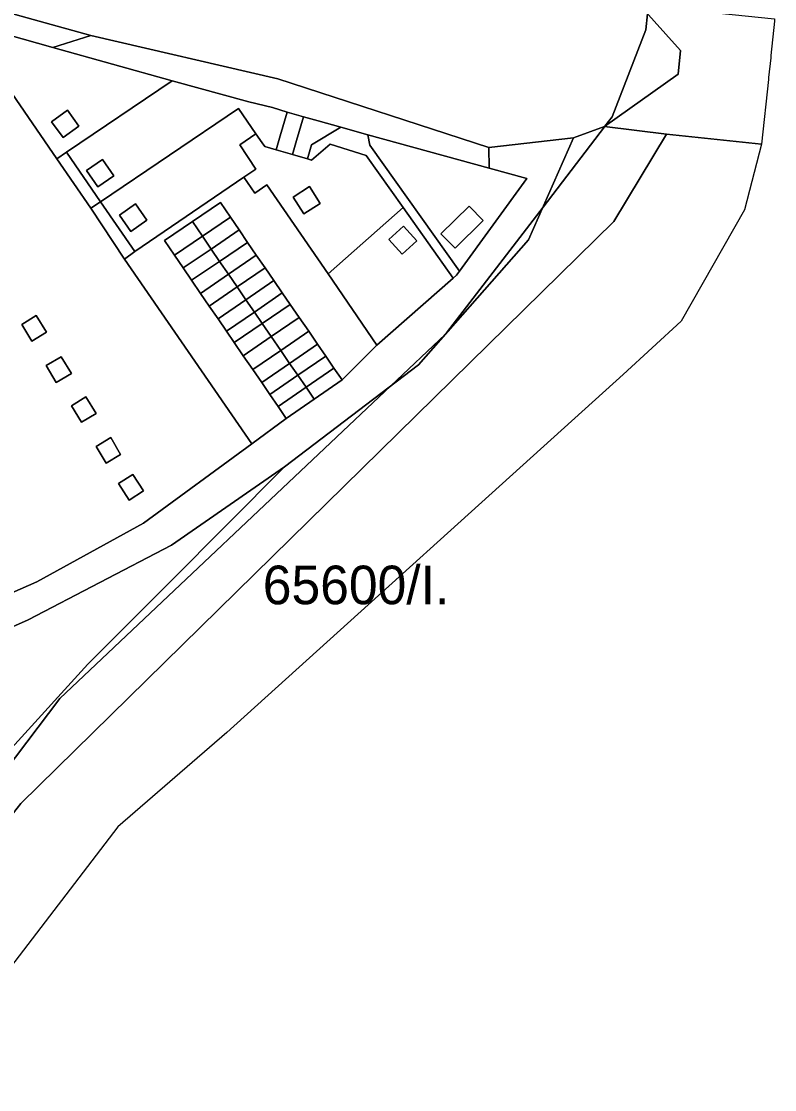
# Model space of a CAD drawing. Extents: x -502026 to -497664, y -1143484 to -1138019.
# Drawn here: x -497820 to -497663.8, y -1140882.6 to -1140661.2 of the extents above; entities that cross this region are included whole.
import ezdxf

# ---------------------------------------------------------------- set-up
doc = ezdxf.new("R2010")
doc.units = 0
for name, color, linetype in [('25', 7, 'Continuous'), ('37', 7, 'Continuous'), ('49', 7, 'Continuous'), ('55', 7, 'Continuous'), ('62', 7, 'Continuous'), ('7', 7, 'Continuous')]:
    doc.layers.add(name, color=color, linetype=linetype)

msp = doc.modelspace()

# ---------------------------------------------------------------- linework, layer by layer
at = {"layer": '25'}
for points in [[(-497805.55, -1140664.16), (-497813.42, -1140666.63), (-497832.11, -1140661.41), (-497812.62, -1140689.68), (-497805.57, -1140699.94), (-497798.59, -1140710.5), (-497772.17, -1140748.77), (-497794.67, -1140765.2), (-497816.79, -1140777.36), (-497824.82, -1140780.89), (-497825.15, -1140780.18), (-497841.74, -1140744.45), (-497858.43, -1140708.44), (-497861.67, -1140701.6), (-497877.43, -1140665.94), (-497897.52, -1140673.81), (-497916.16, -1140638.1), (-497908.61, -1140635.26), (-497911.38, -1140628.95), (-497891.85, -1140619.36), (-497883.28, -1140625.68), (-497860.05, -1140644.73), (-497839.03, -1140654.82)], [(-497814.79, -1140725.62), (-497816.92, -1140722.2), (-497819.9, -1140724.05), (-497817.78, -1140727.49)], [(-497809.61, -1140734.21), (-497811.69, -1140730.73), (-497814.8, -1140732.5), (-497812.75, -1140736.05)], [(-497804.5, -1140742.48), (-497806.63, -1140739.05), (-497809.61, -1140740.89), (-497807.51, -1140744.29)], [(-497799.39, -1140750.98), (-497801.41, -1140747.43), (-497804.48, -1140749.3), (-497802.41, -1140752.77)], [(-497794.69, -1140758.46), (-497796.88, -1140755.08), (-497799.83, -1140756.99), (-497797.64, -1140760.41)]]:
    msp.add_lwpolyline(points, close=True, dxfattribs=at)
at = {"layer": '37'}
for points in [[(-497813.42, -1140666.63), (-497788.69, -1140673.54), (-497810.63, -1140688.34), (-497812.62, -1140689.68), (-497832.11, -1140661.41)], [(-497723.05, -1140687.37), (-497722.99, -1140691.64), (-497748.17, -1140684.73), (-497753.73, -1140683.13), (-497758.48, -1140681.82), (-497761.46, -1140681.02), (-497764.9, -1140680.06), (-497767.93, -1140679.05), (-497772.82, -1140677.87), (-497788.69, -1140673.54), (-497813.42, -1140666.63), (-497805.55, -1140664.16), (-497766.84, -1140673.11)], [(-497764.9, -1140680.06), (-497766.31, -1140684.95), (-497767.16, -1140687.87), (-497769.5, -1140687.17), (-497770.07, -1140686.37), (-497771.35, -1140684.52), (-497774.94, -1140679.25), (-497803.58, -1140698.6), (-497810.63, -1140688.34), (-497788.69, -1140673.54), (-497772.82, -1140677.87), (-497767.93, -1140679.05)], [(-497808.03, -1140682.91), (-497810.44, -1140679.64), (-497813.72, -1140682.05), (-497811.31, -1140685.32)], [(-497771.35, -1140684.52), (-497774.68, -1140686.78), (-497771.36, -1140691.82), (-497773.83, -1140693.5), (-497796.43, -1140708.94), (-497803.58, -1140698.6), (-497774.94, -1140679.25)], [(-497761.46, -1140681.02), (-497762.91, -1140685.94), (-497763.75, -1140688.84), (-497767.16, -1140687.87), (-497766.31, -1140684.95), (-497764.9, -1140680.06)], [(-497753.73, -1140683.13), (-497759.86, -1140686.8), (-497760.69, -1140689.73), (-497763.75, -1140688.84), (-497762.91, -1140685.94), (-497761.46, -1140681.02), (-497758.48, -1140681.82)], [(-497767.16, -1140687.87), (-497763.75, -1140688.84), (-497760.69, -1140689.73), (-497759.83, -1140689.95), (-497755.93, -1140686.66), (-497748.49, -1140689), (-497740.84, -1140699.76), (-497756.35, -1140713.53), (-497769.08, -1140695.11), (-497771.55, -1140696.82), (-497773.83, -1140693.5), (-497771.36, -1140691.82), (-497774.68, -1140686.78), (-497771.35, -1140684.52), (-497770.07, -1140686.37), (-497769.5, -1140687.17)], [(-497748.17, -1140684.73), (-497747.74, -1140686.86), (-497729.17, -1140712.99), (-497729.76, -1140713.83), (-497730.5, -1140714.46), (-497740.84, -1140699.76), (-497748.49, -1140689), (-497755.93, -1140686.66), (-497759.83, -1140689.95), (-497760.69, -1140689.73), (-497759.86, -1140686.8), (-497753.73, -1140683.13)], [(-497722.99, -1140691.64), (-497715.23, -1140693.81), (-497729.17, -1140712.99), (-497747.74, -1140686.86), (-497748.17, -1140684.73)], [(-497803.58, -1140698.6), (-497805.57, -1140699.94), (-497812.62, -1140689.68), (-497810.63, -1140688.34)], [(-497800.84, -1140693.2), (-497803.17, -1140689.85), (-497806.48, -1140692.15), (-497804.15, -1140695.5)], [(-497756.35, -1140713.53), (-497746.3, -1140728.34), (-497753.47, -1140735.53), (-497755.17, -1140733.05), (-497756.86, -1140730.58), (-497758.56, -1140728.1), (-497760.41, -1140725.42), (-497762.39, -1140722.56), (-497764.23, -1140719.92), (-497765.89, -1140717.49), (-497767.64, -1140714.93), (-497769.45, -1140712.29), (-497771.27, -1140709.66), (-497773.09, -1140707.01), (-497774.82, -1140704.44), (-497776.61, -1140701.8), (-497778.72, -1140698.77), (-497784.51, -1140702.69), (-497790.29, -1140706.6), (-497788.22, -1140709.66), (-497786.43, -1140712.3), (-497784.7, -1140714.86), (-497782.83, -1140717.58), (-497781.02, -1140720.22), (-497779.21, -1140722.86), (-497777.48, -1140725.43), (-497775.89, -1140727.79), (-497774.02, -1140730.52), (-497772.02, -1140733.38), (-497770.16, -1140736.05), (-497768.46, -1140738.53), (-497766.77, -1140741), (-497765.07, -1140743.48), (-497772.17, -1140748.77), (-497798.59, -1140710.5), (-497796.43, -1140708.94), (-497773.83, -1140693.5), (-497771.55, -1140696.82), (-497769.08, -1140695.11)], [(-497758.04, -1140698.94), (-497760.26, -1140695.45), (-497763.62, -1140697.63), (-497761.39, -1140701.07)], [(-497796.43, -1140708.94), (-497798.59, -1140710.5), (-497805.57, -1140699.94), (-497803.58, -1140698.6)], [(-497793.95, -1140702.41), (-497796.31, -1140699.06), (-497799.65, -1140701.41), (-497797.28, -1140704.76)], [(-497730.5, -1140714.46), (-497746.3, -1140728.34), (-497756.35, -1140713.53), (-497740.84, -1140699.76)], [(-497724.24, -1140702.5), (-497727.17, -1140699.5), (-497732.99, -1140705.26), (-497730.06, -1140708.25)], [(-497738.01, -1140706.73), (-497740.73, -1140703.68), (-497743.79, -1140706.41), (-497741.07, -1140709.46)]]:
    msp.add_lwpolyline(points, close=True, dxfattribs=at)
at = {"layer": '49'}
msp.add_lwpolyline([(-497681.38, -1140658.88), (-497663.84, -1140660.72), (-497663.83, -1140661.21), (-497664.59, -1140668.32), (-497664.63, -1140668.75), (-497665.07, -1140672.88), (-497665.12, -1140673.27), (-497666.55, -1140686.68), (-497686.23, -1140684.57), (-497699.12, -1140683.04), (-497683.84, -1140672.19), (-497683.37, -1140667.28), (-497691.84, -1140657.78)], close=True, dxfattribs=at)
msp.add_lwpolyline([(-497858.16, -1140885.44), (-497844.62, -1140856.7), (-497835.62, -1140846.8), (-497830.01, -1140835.82), (-497820.05, -1140823.31), (-497697.18, -1140702.68), (-497686.23, -1140684.57), (-497666.55, -1140686.68), (-497670.07, -1140700.29), (-497683.21, -1140723.36), (-497695.22, -1140734.41), (-497777.39, -1140808.57), (-497799.97, -1140828.11), (-497824, -1140859.5), (-497836.97, -1140877.6), (-497854.91, -1140905.15)], dxfattribs=at)
at = {"layer": '55'}
for points in [[(-497691.84, -1140657.78), (-497683.37, -1140667.28), (-497683.84, -1140672.19), (-497699.12, -1140683.04), (-497705.51, -1140685.39), (-497723.05, -1140687.37), (-497766.84, -1140673.11), (-497805.55, -1140664.16), (-497839.03, -1140654.82)], [(-497880.69, -1140905.18), (-497860.49, -1140863.16), (-497854.48, -1140854.34), (-497850.96, -1140849.17), (-497835.81, -1140826.92), (-497806.18, -1140794.39), (-497789.21, -1140777.41), (-497765.45, -1140753.54), (-497737.64, -1140732.37), (-497714.85, -1140706.52), (-497705.51, -1140685.39), (-497699.12, -1140683.04), (-497686.23, -1140684.57), (-497697.18, -1140702.68), (-497820.05, -1140823.31), (-497830.01, -1140835.82), (-497835.62, -1140846.8), (-497844.62, -1140856.7), (-497858.16, -1140885.44)], [(-497824.82, -1140780.89), (-497816.79, -1140777.36), (-497794.67, -1140765.2), (-497772.17, -1140748.77), (-497765.07, -1140743.48), (-497759.27, -1140739.51), (-497753.47, -1140735.53), (-497746.3, -1140728.34), (-497730.5, -1140714.46), (-497729.76, -1140713.83), (-497729.17, -1140712.99), (-497715.23, -1140693.81), (-497722.99, -1140691.64), (-497723.05, -1140687.37), (-497705.51, -1140685.39), (-497714.85, -1140706.52), (-497737.64, -1140732.37), (-497765.45, -1140753.54), (-497788.84, -1140769.76), (-497818.59, -1140785.2), (-497851.87, -1140799.97)]]:
    msp.add_lwpolyline(points, dxfattribs=at)
for points in [[(-497808.03, -1140682.91), (-497811.31, -1140685.32), (-497813.72, -1140682.05), (-497810.44, -1140679.64)], [(-497800.84, -1140693.2), (-497804.15, -1140695.5), (-497806.48, -1140692.15), (-497803.17, -1140689.85)], [(-497758.04, -1140698.94), (-497761.39, -1140701.07), (-497763.62, -1140697.63), (-497760.26, -1140695.45)], [(-497793.95, -1140702.41), (-497797.28, -1140704.76), (-497799.65, -1140701.41), (-497796.31, -1140699.06)], [(-497776.61, -1140701.8), (-497782.44, -1140705.74), (-497784.51, -1140702.69), (-497778.72, -1140698.77)], [(-497724.24, -1140702.5), (-497730.06, -1140708.25), (-497732.99, -1140705.26), (-497727.17, -1140699.5)], [(-497782.44, -1140705.74), (-497788.22, -1140709.66), (-497790.29, -1140706.6), (-497784.51, -1140702.69)], [(-497774.82, -1140704.44), (-497780.65, -1140708.39), (-497782.44, -1140705.74), (-497776.61, -1140701.8)], [(-497773.09, -1140707.01), (-497778.91, -1140710.95), (-497780.65, -1140708.39), (-497774.82, -1140704.44)], [(-497738.01, -1140706.73), (-497741.07, -1140709.46), (-497743.79, -1140706.41), (-497740.73, -1140703.68)], [(-497780.65, -1140708.39), (-497786.43, -1140712.3), (-497788.22, -1140709.66), (-497782.44, -1140705.74)], [(-497771.27, -1140709.66), (-497777.06, -1140713.63), (-497778.91, -1140710.95), (-497773.09, -1140707.01)], [(-497778.91, -1140710.95), (-497784.7, -1140714.86), (-497786.43, -1140712.3), (-497780.65, -1140708.39)], [(-497769.45, -1140712.29), (-497775.24, -1140716.26), (-497777.06, -1140713.63), (-497771.27, -1140709.66)], [(-497777.06, -1140713.63), (-497782.83, -1140717.58), (-497784.7, -1140714.86), (-497778.91, -1140710.95)], [(-497775.24, -1140716.26), (-497781.02, -1140720.22), (-497782.83, -1140717.58), (-497777.06, -1140713.63)], [(-497767.64, -1140714.93), (-497773.43, -1140718.9), (-497775.24, -1140716.26), (-497769.45, -1140712.29)], [(-497773.43, -1140718.9), (-497779.21, -1140722.86), (-497781.02, -1140720.22), (-497775.24, -1140716.26)], [(-497765.89, -1140717.49), (-497771.67, -1140721.45), (-497773.43, -1140718.9), (-497767.64, -1140714.93)], [(-497764.23, -1140719.92), (-497770.06, -1140723.79), (-497771.67, -1140721.45), (-497765.89, -1140717.49)], [(-497771.67, -1140721.45), (-497777.48, -1140725.43), (-497779.21, -1140722.86), (-497773.43, -1140718.9)], [(-497762.39, -1140722.56), (-497768.19, -1140726.53), (-497770.06, -1140723.79), (-497764.23, -1140719.92)], [(-497814.79, -1140725.62), (-497817.78, -1140727.49), (-497819.9, -1140724.05), (-497816.92, -1140722.2)], [(-497770.06, -1140723.79), (-497775.89, -1140727.79), (-497777.48, -1140725.43), (-497771.67, -1140721.45)], [(-497760.41, -1140725.42), (-497766.21, -1140729.4), (-497768.19, -1140726.53), (-497762.39, -1140722.56)], [(-497768.19, -1140726.53), (-497774.02, -1140730.52), (-497775.89, -1140727.79), (-497770.06, -1140723.79)], [(-497766.21, -1140729.4), (-497772.02, -1140733.38), (-497774.02, -1140730.52), (-497768.19, -1140726.53)], [(-497758.56, -1140728.1), (-497764.36, -1140732.08), (-497766.21, -1140729.4), (-497760.41, -1140725.42)], [(-497764.36, -1140732.08), (-497770.16, -1140736.05), (-497772.02, -1140733.38), (-497766.21, -1140729.4)], [(-497756.86, -1140730.58), (-497762.66, -1140734.55), (-497764.36, -1140732.08), (-497758.56, -1140728.1)], [(-497809.61, -1140734.21), (-497812.75, -1140736.05), (-497814.8, -1140732.5), (-497811.69, -1140730.73)], [(-497755.17, -1140733.05), (-497760.97, -1140737.03), (-497762.66, -1140734.55), (-497756.86, -1140730.58)], [(-497762.66, -1140734.55), (-497768.46, -1140738.53), (-497770.16, -1140736.05), (-497764.36, -1140732.08)], [(-497753.47, -1140735.53), (-497759.27, -1140739.51), (-497760.97, -1140737.03), (-497755.17, -1140733.05)], [(-497760.97, -1140737.03), (-497766.77, -1140741), (-497768.46, -1140738.53), (-497762.66, -1140734.55)], [(-497759.27, -1140739.51), (-497765.07, -1140743.48), (-497766.77, -1140741), (-497760.97, -1140737.03)], [(-497804.5, -1140742.48), (-497807.51, -1140744.29), (-497809.61, -1140740.89), (-497806.63, -1140739.05)], [(-497799.39, -1140750.98), (-497802.41, -1140752.77), (-497804.48, -1140749.3), (-497801.41, -1140747.43)], [(-497794.69, -1140758.46), (-497797.64, -1140760.41), (-497799.83, -1140756.99), (-497796.88, -1140755.08)]]:
    msp.add_lwpolyline(points, close=True, dxfattribs=at)
at = {"layer": '62'}
for points in [[(-497690.17, -1140659.65), (-497690.5, -1140663), (-497697.5, -1140681), (-497699, -1140682.95), (-497699.07, -1140683.05), (-497711.83, -1140699.7), (-497731.84, -1140725.79), (-497732, -1140726), (-497732.14, -1140726.13), (-497743.38, -1140736.74), (-497812, -1140801.5), (-497846.5, -1140847), (-497866, -1140892), (-497881, -1140941.5), (-497900, -1141058.5), (-497913.5, -1141102), (-498045.5, -1141384)], [(-498045.5, -1141384), (-497913.5, -1141102), (-497900, -1141058.5), (-497881, -1140941.5), (-497866, -1140892), (-497846.5, -1140847), (-497812, -1140801.5), (-497743.38, -1140736.74), (-497732.14, -1140726.13), (-497732, -1140726), (-497731.84, -1140725.79), (-497711.83, -1140699.7), (-497699.07, -1140683.05), (-497699, -1140682.95), (-497697.5, -1140681), (-497690.5, -1140663), (-497690.17, -1140659.65)], [(-497663.83, -1140661.21), (-497664.59, -1140668.32), (-497664.63, -1140668.75), (-497665.07, -1140672.88), (-497665.12, -1140673.27), (-497666.55, -1140686.68), (-497670.07, -1140700.29), (-497683.21, -1140723.36), (-497695.22, -1140734.41), (-497777.39, -1140808.57), (-497799.97, -1140828.11), (-497824, -1140859.5), (-497836.97, -1140877.6), (-497854.91, -1140905.15), (-497866.12, -1140928.06), (-497869.81, -1140951.44), (-497873.17, -1140978.35), (-497875.52, -1141000), (-497875.68, -1141001.48), (-497876.63, -1141010.16), (-497882.24, -1141061.82), (-497903.42, -1141126.29)]]:
    msp.add_lwpolyline(points, dxfattribs=at)
at = {"layer": '7'}
msp.add_lwpolyline([(-497850.96, -1140849.17), (-497851.16, -1140818.43), (-497853.39, -1140803.07), (-497851.87, -1140799.97), (-497818.59, -1140785.2), (-497788.84, -1140769.76), (-497765.45, -1140753.54), (-497789.21, -1140777.41), (-497806.18, -1140794.39), (-497835.81, -1140826.92)], close=True, dxfattribs=at)

# ---------------------------------------------------------------- texts
at = {"layer": '62'}
msp.add_text('65600/I.', height=8, dxfattribs=at).set_placement((-497769.93, -1140781.99))

doc.saveas('drawing.dxf')
